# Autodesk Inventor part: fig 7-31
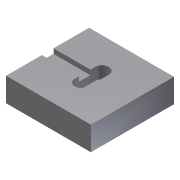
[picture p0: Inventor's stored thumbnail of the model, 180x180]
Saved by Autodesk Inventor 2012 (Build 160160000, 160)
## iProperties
Created: 2004-05
Part Number: fig 7-31
Document SubType Name: Modeling
Designer: CADCIM Technologies
Manufacturer: Standard
Standards Organization: Custom
Density: 1 g/cm^3
Material: Default
Author: CADCIM Technologies
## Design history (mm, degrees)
sketch "Sketch1"
  geometry: L1 (-30.233, -25.517)-(22.302, -25.517); L2 (22.302, -25.517)-(22.302, 25.904); L3 (22.302, 25.904)-(-30.233, 25.904); L4 (-30.233, 25.904)-(-30.233, -25.517)
  constraints: 8 end point, 2 parallel, 1 horizontal, 1 perpendicular
extrude "Extrusion1" new body sketch "Sketch1" distance "d0" = 14.75; taper "d1" = 0 deg
sketch "Sketch2"
  geometry: L1 (1.047, -5.75)-(1.047, 6.846); L2 (-7.35, 6.845)-(-7.35, -5.75); A1 r 4.198 centre (-3.152, 6.846) between (1.047, 6.846) and (-7.35, 6.845); A2 r 4.198 centre (-3.152, -5.75) between (-7.35, -5.75) and (1.047, -5.75)
  constraints: 4 end point, 4 point on circle, 4 tangent, 2 centre point, 1 parallel
extrude "Extrusion2" cut sketch "Sketch2" distance "d2" = 7.5; taper "d3" = 0 deg
sketch "Sketch3"
  geometry: L1 (-7.5, 0)-(-7.5, 12.595) reference; L2 (-7.5, 0)-(0, 0) reference; L3 (-7.5, 2.416)-(-4.537, 2.416); L4 (-4.537, 2.416)-(-4.537, 9.616); L5 (-4.537, 9.616)-(-7.5, 9.616)
  constraints: 6 end point, 2 perpendicular, 2 point on line, 1 parallel
extrude "Extrusion3" cut sketch "Sketch3" stored distance "d4" = 6.75; taper "d5" = 0 deg
body "Solid1"
